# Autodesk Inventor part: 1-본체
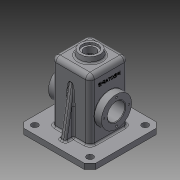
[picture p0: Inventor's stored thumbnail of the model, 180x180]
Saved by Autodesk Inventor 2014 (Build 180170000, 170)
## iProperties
Created: 2016-02
Part Number: 1-본체
Material: 일반
Document SubType Name: Modeling
Designer: Administrator
Density: 1 g/cm^3
Appearance: 기본값
Author: Administrator
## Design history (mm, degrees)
sketch "스케치1"
  geometry: L1 (-35, 35)-(35, 35); L2 (35, 35)-(35, -35); L3 (35, -35)-(-35, -35); L4 (-35, -35)-(-35, 35); 3 further points
  constraints: 8 end point, 2 midpoint, 2 parallel, 1 horizontal, 1 horizontal alignment, 1 perpendicular, 1 vertical alignment
  dimensions: "d0" = 70 distance of L1.start L1.end; "d1" = 70 distance of L1.end L2.end
extrude "돌출1" new body sketch "스케치1" distance "d2" = 120; taper "d3" = 0 deg
sketch "스케치2"
  geometry: L1 (65, -65)-(-65, -65); L2 (-65, -65)-(-65, 65); L3 (-65, 65)-(65, 65); L4 (65, 65)-(65, -65); 3 further points
  constraints: 8 end point, 2 midpoint, 2 parallel, 2 perpendicular, 1 horizontal, 1 horizontal alignment, 1 vertical alignment
  dimensions: "d4" = 130 distance of L1.start L1.end
extrude "돌출3" join sketch "스케치2" distance "d7" = 10; taper "d8" = 0 deg
sketch "스케치4"
  geometry: C1 r 20 at (0, 0); 1 further point
  constraints: 1 centre point, 1 coincident
  dimensions: "d10" = 40 diameter of C1
extrude "돌출4" join sketch "스케치4" distance "d11" = 10; taper "d12" = -10 deg
sketch "스케치5"
  geometry: L1 (-50, 10)-(50, 10); L2 (50, 10)-(30.604, 120); L3 (30.604, 120)-(-30.604, 120); L4 (-30.604, 120)-(-50, 10); L5 (65, 10)-(-65, 10) reference; L6 (35, 120)-(-35, 120) reference; 3 further points
  constraints: 8 end point, 2 collinear, 2 midpoint, 2 vertical alignment, 1 equal length, 1 horizontal, 1 parallel
  dimensions: "d14" = 100 deg angle of L2 L5; "d15" = 15 distance of L5.start L1.end
sketch "스케치6"
  geometry: C1 r 27.5 at (0, 55); 1 further point
  constraints: 1 centre point, 1 vertical alignment
  dimensions: "d16" = 55 diameter of C1; "d17" = 55 distance of point (0, 0) C1.centre
extrude "돌출5" join sketch "스케치6" stored distance "d18" = 96; taper "d19" = 0 deg
sketch "스케치7"
  geometry: L1 (0, 0)-(-50, 50); L2 (65, 65)-(-65, 65) reference; L3 (-65, 65)-(-65, -65) reference
  constraints: 2 end point
  dimensions: "d21" = 15 horizontal distance of L2.end L1.end; "d22" = 15 distance from line of L1.end L3
hole "구멍1" sketch "스케치7" at (-50, 50) diameter "d23" = 12; stored, may be unused: countersink angle "d27" = 90 deg, drill point angle "d29" = 118 deg; dims "d24" = 6, "d25" = 4, "d26" = 2, "d28" = 8
extrude "돌출6" join sketch "스케치5" stored distance "d33" = 10; taper "d34" = 0 deg
sketch "스케치9"
  geometry: L1 (30, 115)-(-30, 115); L2 (-30, 115)-(-30, 0); L3 (-30, 0)-(30, 0); L4 (30, 0)-(30, 115); L5 (-35, 120)-(35, 120) reference; L6 (-35, 10)-(-35, 120) reference; 2 further points
  constraints: 8 end point, 2 midpoint, 2 parallel, 1 horizontal, 1 perpendicular, 1 vertical alignment
  dimensions: "d38" = 5 distance between parallel lines of L5 L1; "d39" = 5 distance between parallel lines of L6 L2
extrude "돌출7" cut sketch "스케치9" stored distance "d40" = 60; taper "d41" = 0 deg
sketch "스케치10"
  geometry: C1 r 27.5 at (60, 30) reference; C2 r 27.5 at (60, 30); 1 further point
  constraints: 1 centre point, 1 coincident
  dimensions: "d42" = 55 diameter of C2
extrude "돌출8" join sketch "스케치10" distance "d43" = 7; taper "d44" = -45 deg
sketch "스케치11"
  geometry: L1 (0, 0)-(22.5, 0); C1 r 27.5 at (0, 0) reference; 1 further point
  constraints: 2 end point, 1 horizontal
  dimensions: "d45" = 22.5 distance of L1.start L1.end
hole "구멍2" sketch "스케치11" at (22.5, 0) diameter "d46" = 3.242; stored, may be unused: countersink angle "d50" = 90 deg, drill point angle "d52" = 118 deg; dims "d47" = 8, "d48" = 4, "d49" = 2, "d51" = 10
hole "구멍3" diameter "d58" = 32; stored, may be unused: countersink angle "d62" = 90 deg, drill point angle "d64" = 118 deg; dims "d56" = 10, "d57" = 10, "d59" = 8, "d60" = 4, "d61" = 2, "d63" = 10
hole "구멍4" diameter "d67" = 21; stored, may be unused: countersink angle "d71" = 90 deg, drill point angle "d73" = 118 deg; dims "d65" = 10, "d66" = 10, "d68" = 8, "d69" = 28, "d70" = 4, "d72" = 10
fillet "모깎기1" dims "d74" = 8
fillet "모깎기2" dims "d75" = 8
chamfer "모따기1" distance "d76" = 10; stored, may be unused: second distance "d77" = 2, angle "d78" = 45 deg
fillet "모깎기3" dims "d79" = 3
fillet "모깎기4" dims "d80" = 3
fillet "모깎기5" dims "d81" = 3
fillet "모깎기6" dims "d82" = 3
fillet "모깎기7" dims "d83" = 3
fillet "모깎기8" dims "d84" = 3
fillet "모깎기9" dims "d85" = 0.5
fillet "모깎기10" dims "d86" = 0.5
chamfer "모따기2" distance "d87" = 1; stored, may be unused: second distance "d88" = 2, angle "d89" = 45 deg
sketch "스케치12"
  geometry: L1 (99, 62)-(0, 62) reference; L2 (-18, 8.763)-(-18, 45.237) reference; 2 further points
  constraints: 1 other
  dimensions: "d90" = 35 distance from line of L1 point (12, 27); "d91" = 30 distance from line of point (12, 27) L2
feature "엠보싱1" sketch "스케치12" dims "d0" = 70, "d1" = 70, "d92" = 0.5, "d93" = 0
node "솔리드1"
pattern_circular "원형 패턴1" dims angle "d31" = 360 deg
pattern_circular "원형 패턴2" dims angle "d54" = 360 deg
mirror "대칭1"
